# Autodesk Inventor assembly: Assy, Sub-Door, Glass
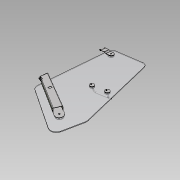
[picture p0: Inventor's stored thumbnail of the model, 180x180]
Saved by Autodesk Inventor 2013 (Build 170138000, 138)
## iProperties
Shininess: 64.0
Length Units: 11269
Angle Units: 11279
Time Units: 11290
Mass Units: 11283
Length Display Precision: 3
Angle Display Precision: 2
Compacted: True
Created: 2005-02
Part Number: Assy, Sub-Door, Glass
Document SubType Name: Assembly
Designer: =<Author>
Manufacturer: Standard
Standards Organization: Custom
Description: =<Part Number>
Mass: 10535.8 g
Surface Area: 16971.1 cm^2
Volume: 5677.68 cm^3
Density: 1.85565 g/cm^3
Density: 0.0
Volumn: 0.0
Area: 0.0
PropertySet Name: Model Information
Control State: 0
Master: False
Checked Out: False
Author: PVitaliy
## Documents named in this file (10)
- Y:\Dropbox\Launch 2013\Eco Material Advisor\Assy, Door\_Data\Assy, Cab\Assy, Sub-Door, Glass.iam
- Y:\Dropbox\Launch 2013\Eco Material Advisor\Assy, Door\_Data\Assy, Cab\Glass door.ipt
- Y:\Dropbox\Launch 2013\Eco Material Advisor\Assy, Door\_Data\Assy, Cab\glass hinge.iam
- Y:\Dropbox\Launch 2013\Eco Material Advisor\Assy, Door\_Data\Assy, Cab\rubber ring.ipt
- Y:\Dropbox\Launch 2013\Eco Material Advisor\Assy, Door\_Data\Assy, Cab\Large glass hinge.iam
- Y:\Dropbox\Launch 2013\Eco Material Advisor\Assy, Door\_Data\Assy, Cab\PK46.51.13.003.ipt
- Y:\Dropbox\Launch 2013\Eco Material Advisor\Assy, Door\_Data\Assy, Cab\handle on the glass-2.iam
- Y:\Dropbox\Launch 2013\Eco Material Advisor\Assy, Door\_Data\Assy, Cab\PK46.51.13.005.ipt
- Y:\Dropbox\Launch 2013\Eco Material Advisor\Assy, Door\_Data\Assy, Cab\PK46.51.13.040.iam
- Y:\Dropbox\Launch 2013\Eco Material Advisor\Assy, Door\_Data\Assy, Cab\M10-6H.5.019(S16).ipt
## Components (22 placed, 9 different names)
1. glass hinge:1 [sub-assembly] — Insert:1, Angle:1
2. Large glass hinge:1 [sub-assembly] — Insert:2, Insert:3
3. handle on the glass-2:1 [sub-assembly] — Insert:32, Mate:5, Insert:33, Mate:6
4. PK46.51.13.040:1 [sub-assembly] — Insert:30, Mate:1, Mate:2
5. PK46.51.13.040:2 [sub-assembly] — Insert:31, Mate:3, Mate:4
6. Glass door:1 — Insert:4, Insert:5, Insert:6, Insert:7, Insert:8, Angle:1, Insert:9, Insert:26, Insert:27, Insert:28, Insert:29
7. rubber ring:1 — Insert:1, Insert:4
8. rubber ring:2 — Insert:5, Insert:10
9. rubber ring:5 — Insert:9, Insert:12
10. rubber ring:6 — Insert:2, Insert:8
11. rubber ring:3 — Insert:3, Insert:6
12. rubber ring:4 — Insert:7, Insert:11
13. PK46.51.13.003:1 — Insert:10, Insert:23
14. PK46.51.13.003:2 — Insert:12, Insert:25
15. PK46.51.13.003:3 — Insert:11, Insert:24
16. PK46.51.13.005:1 — Insert:26, Mate:4, Insert:32, Mate:5
17. PK46.51.13.005:2 — Insert:28, Mate:2, Insert:33, Mate:6
18. PK46.51.13.005:3 — Insert:29, Insert:31, Mate:3
19. PK46.51.13.005:4 — Insert:27, Insert:30, Mate:1
20. M10-6H.5.019(S16):1 — Insert:23
21. M10-6H.5.019(S16):2 — Insert:24
22. M10-6H.5.019(S16):3 — Insert:25
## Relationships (30: Insert 23, Mate 6, Angle 1)
- Insert:1: glass hinge:1 ↔ rubber ring:1
- Insert:2: Large glass hinge:1 ↔ rubber ring:6
- Insert:3: Large glass hinge:1 ↔ rubber ring:3
- Insert:4: Glass door:1 ↔ rubber ring:1
- Insert:5: Glass door:1 ↔ rubber ring:2
- Insert:6: Glass door:1 ↔ rubber ring:3
- Insert:7: Glass door:1 ↔ rubber ring:4
- Insert:8: Glass door:1 ↔ rubber ring:6
- Angle:1: glass hinge:1 ↔ Glass door:1
- Insert:9: Glass door:1 ↔ rubber ring:5
- Insert:10: rubber ring:2 ↔ PK46.51.13.003:1
- Insert:11: rubber ring:4 ↔ PK46.51.13.003:3
- Insert:12: rubber ring:5 ↔ PK46.51.13.003:2
- Insert:23: PK46.51.13.003:1 ↔ M10-6H.5.019(S16):1
- Insert:24: PK46.51.13.003:3 ↔ M10-6H.5.019(S16):2
- Insert:25: PK46.51.13.003:2 ↔ M10-6H.5.019(S16):3
- Insert:26: Glass door:1 ↔ PK46.51.13.005:1
- Insert:27: Glass door:1 ↔ PK46.51.13.005:4
- Insert:28: Glass door:1 ↔ PK46.51.13.005:2
- Insert:29: Glass door:1 ↔ PK46.51.13.005:3
- Insert:30: PK46.51.13.040:1 ↔ PK46.51.13.005:4
- Mate:1: PK46.51.13.040:1 ↔ PK46.51.13.005:4
- Mate:2: PK46.51.13.040:1 ↔ PK46.51.13.005:2
- Insert:31: PK46.51.13.040:2 ↔ PK46.51.13.005:3
- Mate:3: PK46.51.13.040:2 ↔ PK46.51.13.005:3
- Mate:4: PK46.51.13.040:2 ↔ PK46.51.13.005:1
- Insert:32: handle on the glass-2:1 ↔ PK46.51.13.005:1
- Mate:5: handle on the glass-2:1 ↔ PK46.51.13.005:1
- Insert:33: handle on the glass-2:1 ↔ PK46.51.13.005:2
- Mate:6: handle on the glass-2:1 ↔ PK46.51.13.005:2
